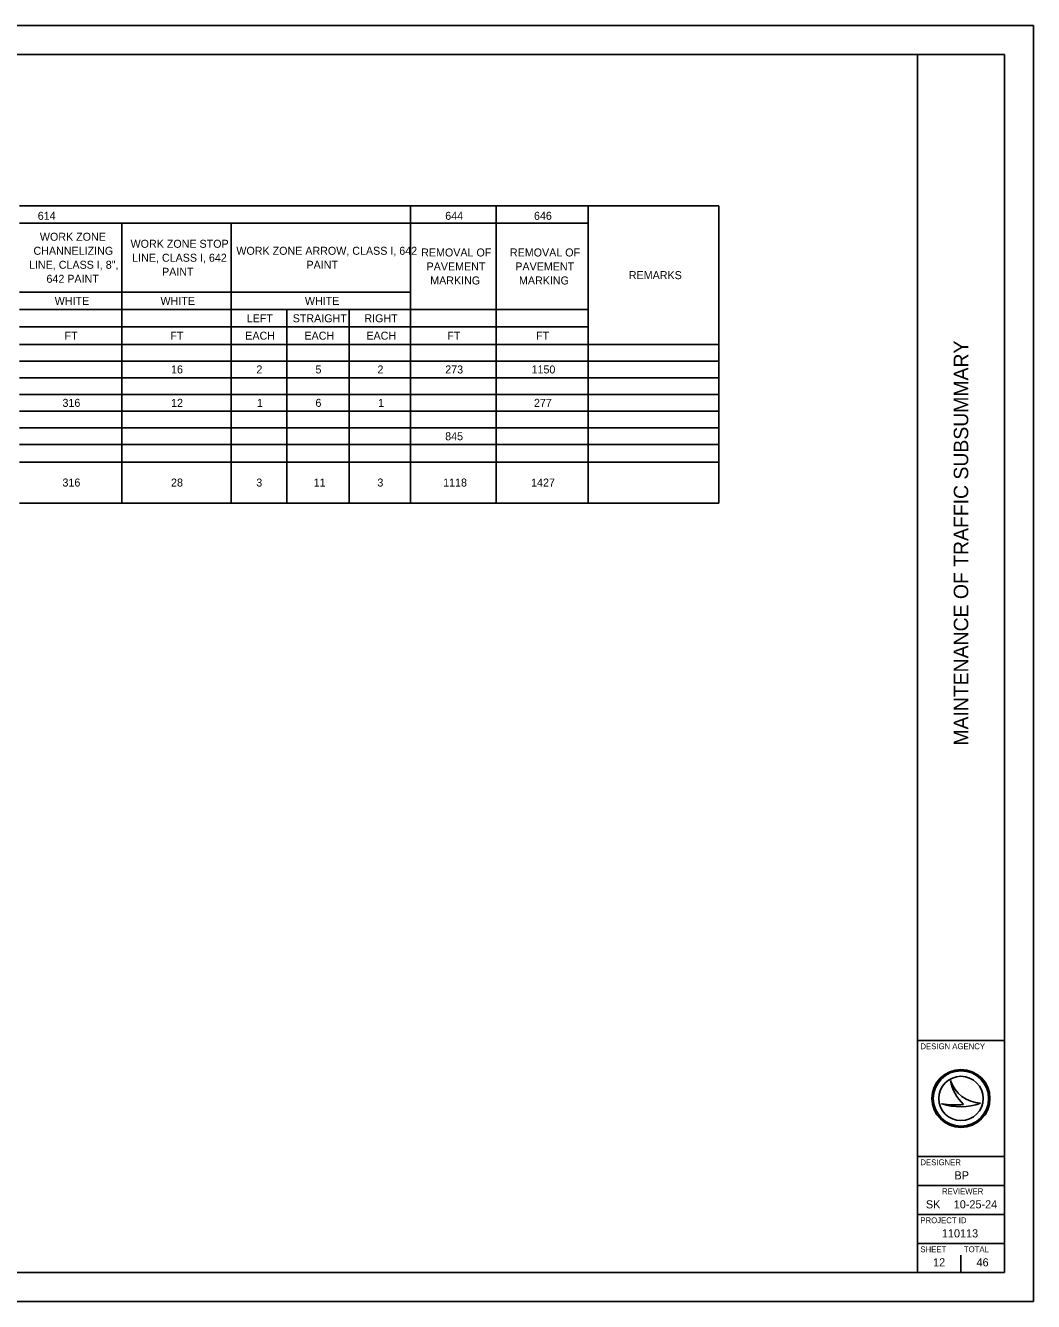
# Model space of a CAD drawing. Extents: x 0 to 34, y 0 to 22.
# Drawn here: x 16.62 to 34, y 0 to 22 of the extents above; entities that cross this region are included whole.
import ezdxf

# ---------------------------------------------------------------- set-up
doc = ezdxf.new("R2010")
doc.units = 0
for name, color, linetype in [('SH_Border', 7, 'Continuous'), ('SH_Cut_Line', 7, 'Continuous'), ('SH_Data', 7, 'Continuous'), ('SH_Text', 7, 'Continuous')]:
    doc.layers.add(name, color=color, linetype=linetype)

msp = doc.modelspace()

# ---------------------------------------------------------------- linework, layer by layer
at = {"layer": 'SH_Border'}
for p, q in [((32, 0.5), (32, 21.5)), ((32, 4.5), (33.5, 4.5)), ((32, 2.5), (33.5, 2.5)), ((32, 2), (33.5, 2)), ((32, 1.5), (33.5, 1.5)), ((32, 1), (33.5, 1))]:
    msp.add_line(p, q, dxfattribs=at)
msp.add_lwpolyline([(1.5, 21.5), (33.5, 21.5), (33.5, 0.5), (1.5, 0.5)], close=True, dxfattribs=at)
at = {"layer": 'SH_Cut_Line'}
msp.add_lwpolyline([(0, 0), (34, 0), (34, 22), (0, 22)], close=True, dxfattribs=at)
at = {"layer": 'SH_Data'}
for p, q in [((32.567, 3.81), (32.567, 3.81)), ((32.417, 3.41), (32.417, 3.41)), ((32.75, 3.5), (32.75, 3.5)), ((33.087, 3.419), (33.087, 3.419)), ((32.375, 0.675), (32.375, 0.675)), ((32.75, 0.5), (32.75, 0.8))]:
    msp.add_line(p, q, dxfattribs=at)
for radius in [0.5, 0.477, 0.477, 0.382]:
    msp.add_circle((32.75, 3.5), radius, dxfattribs=at)
for centre, radius, start, end in [((33.116, 3.998), 0.58, 198.9257, 198.9319), ((33.347, 3.97), 0.796, 191.6379, 191.6421), ((33.116, 3.998), 0.58, 198.9319, 267.1657), ((33.347, 3.97), 0.796, 191.6421, 226.0947), ((32.739, 4.37), 1.013, 251.4576, 290.0832), ((32.648, 4.654), 1.266, 259.4964, 259.4995), ((32.739, 4.37), 1.013, 251.4527, 251.4576), ((32.648, 4.654), 1.266, 259.4995, 276.6672)]:
    msp.add_arc(centre, radius, start, end, dxfattribs=at)
at = {"layer": 'SH_Text'}
for p, q in [((16.515, 18.89), (18.279, 18.89)), ((18.279, 18.89), (28.575, 18.89)), ((23.259, 18.89), (23.259, 17.402)), ((24.735, 18.89), (24.735, 17.402)), ((26.319, 18.89), (26.319, 17.402)), ((28.575, 18.89), (28.575, 17.402)), ((16.515, 18.59), (18.279, 18.59)), ((18.279, 18.59), (26.319, 18.59)), ((18.279, 18.59), (18.279, 17.402)), ((20.163, 18.59), (20.163, 17.402)), ((16.515, 17.402), (18.279, 17.402)), ((18.279, 17.402), (23.259, 17.402)), ((18.279, 17.402), (18.279, 16.214)), ((20.163, 17.402), (20.163, 16.214)), ((23.259, 17.402), (23.259, 16.214)), ((24.735, 17.402), (24.735, 16.214)), ((26.319, 17.402), (26.319, 16.214)), ((28.575, 17.402), (28.575, 16.214)), ((16.515, 17.102), (18.279, 17.102)), ((18.279, 17.102), (26.319, 17.102)), ((21.123, 17.102), (21.123, 16.214)), ((22.203, 17.102), (22.203, 16.214)), ((16.515, 16.802), (18.279, 16.802)), ((18.279, 16.802), (26.319, 16.802)), ((16.515, 16.502), (18.279, 16.502)), ((18.279, 16.502), (28.575, 16.502)), ((16.515, 16.214), (18.279, 16.214)), ((18.279, 16.214), (28.575, 16.214)), ((18.279, 16.214), (18.279, 15.926)), ((20.163, 16.214), (20.163, 15.926)), ((21.123, 16.214), (21.123, 15.926)), ((22.203, 16.214), (22.203, 15.926)), ((23.259, 16.214), (23.259, 15.926)), ((24.735, 16.214), (24.735, 15.926)), ((26.319, 16.214), (26.319, 15.926)), ((28.575, 16.214), (28.575, 15.926)), ((16.515, 15.926), (18.279, 15.926)), ((18.279, 15.926), (28.575, 15.926)), ((18.279, 15.926), (18.279, 15.638)), ((20.163, 15.926), (20.163, 15.638)), ((21.123, 15.926), (21.123, 15.638)), ((22.203, 15.926), (22.203, 15.638)), ((23.259, 15.926), (23.259, 15.638)), ((24.735, 15.926), (24.735, 15.638)), ((26.319, 15.926), (26.319, 15.638)), ((28.575, 15.926), (28.575, 15.638)), ((16.515, 15.638), (18.279, 15.638)), ((18.279, 15.638), (28.575, 15.638)), ((18.279, 15.638), (18.279, 13.766)), ((20.163, 15.638), (20.163, 13.766)), ((21.123, 15.638), (21.123, 13.766)), ((22.203, 15.638), (22.203, 13.766)), ((23.259, 15.638), (23.259, 13.766)), ((24.735, 15.638), (24.735, 13.766)), ((26.319, 15.638), (26.319, 13.766)), ((28.575, 15.638), (28.575, 13.766)), ((16.515, 15.35), (18.279, 15.35)), ((18.279, 15.35), (28.575, 15.35)), ((16.515, 15.062), (18.279, 15.062)), ((18.279, 15.062), (28.575, 15.062)), ((16.515, 14.774), (18.279, 14.774)), ((18.279, 14.774), (28.575, 14.774)), ((16.515, 14.474), (18.279, 14.474)), ((18.279, 14.474), (28.575, 14.474)), ((16.515, 13.766), (18.279, 13.766)), ((18.279, 13.766), (28.575, 13.766))]:
    msp.add_line(p, q, dxfattribs=at)

# ---------------------------------------------------------------- texts
at = {"layer": 'SH_Data'}
msp.add_text('MAINTENANCE OF TRAFFIC SUBSUMMARY', height=0.25, rotation=90, dxfattribs=at).set_placement((32.875, 9.584))
for s, height, p in [('DESIGN AGENCY', 0.1, (32.05, 4.35)), ('DESIGNER', 0.1, (32.05, 2.35)), ('BP', 0.14, (32.638, 2.105)), ('REVIEWER', 0.1, (32.422, 1.85)), ('SK', 0.14, (32.145, 1.605)), ('10-25-24', 0.14, (32.625, 1.605)), ('PROJECT ID', 0.1, (32.05, 1.35)), ('110113', 0.14, (32.421, 1.105)), ('SHEET', 0.1, (32.05, 0.85)), ('TOTAL', 0.1, (32.8, 0.85)), ('12', 0.14, (32.269, 0.605)), ('46', 0.14, (33.018, 0.605))]:
    msp.add_text(s, height=height, dxfattribs=at).set_placement(p)
at = {"layer": 'SH_Text'}
for s, p in [('614', (16.831, 18.65)), ('644', (23.857, 18.65)), ('646', (25.387, 18.65)), ('WORK ZONE ', (16.867, 18.289)), ('WORK ZONE STOP ', (18.431, 18.168)), ('CHANNELIZING ', (16.757, 18.047)), ('LINE, CLASS I, 642 ', (18.459, 17.927)), ('WORK ZONE ARROW, CLASS I, 642 ', (20.255, 18.047)), ('REMOVAL OF ', (23.442, 18.018)), ('REMOVAL OF ', (24.972, 18.018)), ('LINE, CLASS I, 8", ', (16.68, 17.806)), ('PAINT', (18.974, 17.685)), ('PAINT', (21.464, 17.806)), ('PAVEMENT ', (23.535, 17.777)), ('PAVEMENT ', (25.065, 17.777)), ('642 PAINT', (16.981, 17.564)), ('MARKING', (23.598, 17.535)), ('MARKING', (25.128, 17.535)), ('REMARKS', (27.023, 17.627)), ('WHITE', (17.123, 17.183)), ('WHITE', (18.947, 17.183)), ('WHITE', (21.437, 17.183)), ('LEFT', (20.433, 16.883)), ('STRAIGHT', (21.227, 16.883)), ('RIGHT', (22.463, 16.883)), ('FT', (17.293, 16.583)), ('FT', (19.117, 16.583)), ('EACH', (20.409, 16.583)), ('EACH', (21.429, 16.583)), ('EACH', (22.497, 16.583)), ('FT', (23.893, 16.583)), ('FT', (25.423, 16.583)), ('16', (19.129, 16.001)), ('2', (20.6, 16.001)), ('5', (21.619, 16.001)), ('2', (22.688, 16.001)), ('273', (23.857, 16.001)), ('1150', (25.345, 16.001)), ('316', (17.257, 15.425)), ('12', (19.13, 15.425)), ('1', (20.611, 15.425)), ('6', (21.619, 15.425)), ('1', (22.699, 15.425)), ('277', (25.387, 15.425)), ('845', (23.856, 14.849)), ('316', (17.257, 14.051)), ('28', (19.129, 14.051)), ('3', (20.599, 14.051)), ('11', (21.589, 14.051)), ('3', (22.687, 14.051)), ('1118', (23.821, 14.051)), ('1427', (25.338, 14.051))]:
    msp.add_text(s, height=0.138, dxfattribs=at).set_placement(p)

doc.saveas('drawing.dxf')
